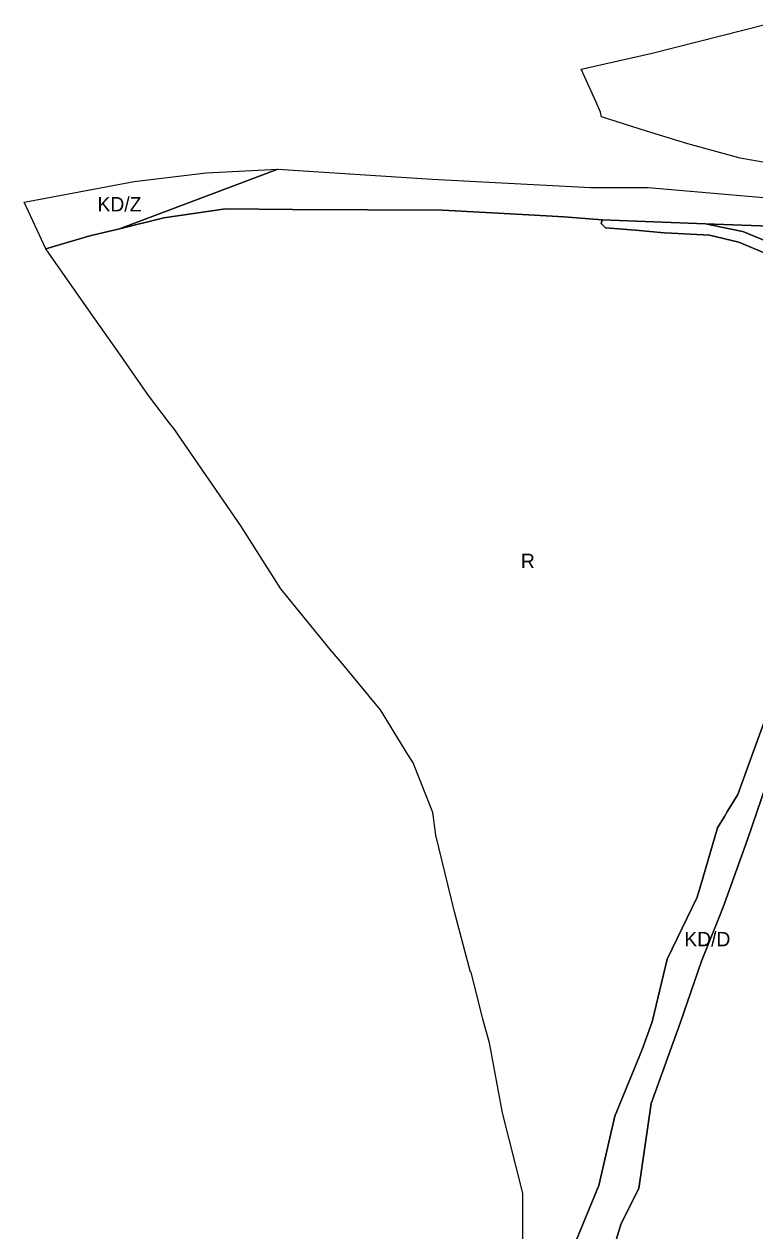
# Model space of a CAD drawing. Extents: x 7438199 to 7440548, y 5549253 to 5551017.
# Drawn here: x 7438199 to 7438706, y 5549912 to 5550749 of the extents above; entities that cross this region are included whole.
import ezdxf

# ---------------------------------------------------------------- set-up
doc = ezdxf.new("R2010")
doc.units = 0
doc.layers.add('linie_rozgraniczajace', color=7, linetype='Continuous')
doc.layers.add('oznaczenia_przeznaczen', color=7, linetype='Continuous')

msp = doc.modelspace()

# ---------------------------------------------------------------- linework, layer by layer
at = {"layer": 'linie_rozgraniczajace'}
for points in [[(7438724.59, 5550650.73), (7438695.64, 5550655.89), (7438659.54, 5550665.82), (7438630.71, 5550674.75), (7438599.57, 5550684.51), (7438598.9, 5550687.86), (7438595.81, 5550694.75), (7438585.51, 5550717.7), (7438594.79, 5550719.76), (7438634.69, 5550728.62), (7438713.89, 5550748.85)], [(7438265.38, 5550607.05), (7438375.26, 5550648.19), (7438482.17, 5550641.29), (7438592, 5550635.56), (7438598.21, 5550635.57), (7438631.96, 5550635.63), (7438719.92, 5550628.01)], [(7438545.03, 5549869.81), (7438545.17, 5549938.29), (7438531.07, 5549994.14), (7438521.86, 5550042.53), (7438517.4, 5550059.08), (7438509.15, 5550091.54), (7438508.68, 5550091.5), (7438497.77, 5550133.42), (7438484.75, 5550186.67), (7438482.61, 5550202.32), (7438468.98, 5550236.75), (7438465.25, 5550242.41), (7438446.34, 5550273.45), (7438446.12, 5550273.72), (7438419.97, 5550305.31), (7438411.8, 5550315.18), (7438377.36, 5550357.27), (7438349.63, 5550401.07), (7438303.17, 5550468.4), (7438300.13, 5550472.27), (7438285.54, 5550491.44), (7438264.41, 5550521.66), (7438245.6, 5550548.42), (7438214.27, 5550593), (7438244.74, 5550601.98), (7438265.38, 5550607.05), (7438296.06, 5550614.59), (7438338.91, 5550620.88), (7438385.44, 5550620.39), (7438489.33, 5550619.92), (7438519.34, 5550618.2), (7438549.07, 5550616.55), (7438573.42, 5550615.16), (7438600.01, 5550613.25), (7438599.47, 5550610.67), (7438602.36, 5550607.7), (7438623.13, 5550605.93), (7438642.95, 5550604.23), (7438648.22, 5550604.04), (7438674.54, 5550602.54), (7438694.83, 5550597.65), (7438713.52, 5550589.86)], [(7438894.22, 5550560.43), (7438887.92, 5550566.48), (7438888.89, 5550567.32), (7438879.39, 5550574.14), (7438873.06, 5550578.68), (7438866.73, 5550583.23), (7438852.19, 5550593.13), (7438838.54, 5550599.62), (7438797, 5550605.68), (7438761.69, 5550606.92), (7438737.96, 5550607.87), (7438716.87, 5550608.71), (7438696.99, 5550609.45), (7438671.7, 5550610.37), (7438600.01, 5550613.25), (7438573.42, 5550615.16), (7438549.07, 5550616.55), (7438519.34, 5550618.2), (7438489.33, 5550619.92), (7438385.44, 5550620.39), (7438338.91, 5550620.88), (7438296.06, 5550614.59), (7438265.38, 5550607.05)], [(7438713.52, 5550589.86), (7438694.83, 5550597.65), (7438674.54, 5550602.54), (7438648.22, 5550604.04), (7438642.95, 5550604.23), (7438623.13, 5550605.93), (7438602.36, 5550607.7), (7438599.47, 5550610.67), (7438600.01, 5550613.25), (7438671.7, 5550610.37), (7438696.25, 5550605.39), (7438697.63, 5550605.18), (7438714.95, 5550597.94)], [(7438716.44, 5550276.4), (7438702.92, 5550238.98), (7438694.2, 5550214.86), (7438687.05, 5550203.15), (7438684.87, 5550199.59), (7438680.01, 5550191.63), (7438669.82, 5550156.79), (7438665.98, 5550143.61), (7438645.21, 5550100.54), (7438636.25, 5550063.9), (7438634.62, 5550057.28), (7438627.81, 5550037.97), (7438608.83, 5549991.81), (7438597.73, 5549943.7), (7438581.96, 5549905.55)], [(7438581.96, 5549905.55), (7438597.73, 5549943.7), (7438608.83, 5549991.81), (7438627.81, 5550037.97), (7438634.62, 5550057.28), (7438636.25, 5550063.9), (7438645.21, 5550100.54), (7438665.98, 5550143.61), (7438669.82, 5550156.79), (7438680.01, 5550191.63), (7438684.87, 5550199.59), (7438687.05, 5550203.15), (7438694.2, 5550214.86), (7438702.92, 5550238.98), (7438716.44, 5550276.4)], [(7438600.02, 5549874.4), (7438613.31, 5549917.27), (7438625.44, 5549941.62), (7438634.15, 5550000.58), (7438654.37, 5550056.83), (7438668.91, 5550099.21), (7438683.92, 5550136.68), (7438700.83, 5550183.58), (7438719.95, 5550239.79)], [(7438719.95, 5550239.79), (7438700.83, 5550183.58), (7438683.92, 5550136.68), (7438668.91, 5550099.21), (7438654.37, 5550056.83), (7438634.15, 5550000.58), (7438625.44, 5549941.62), (7438613.31, 5549917.27), (7438600.02, 5549874.4)]]:
    msp.add_lwpolyline(points, dxfattribs=at)
for points in [[(7438199.3, 5550625.45), (7438275.57, 5550639.78), (7438325.48, 5550645.7), (7438375.26, 5550648.19), (7438265.38, 5550607.05), (7438244.74, 5550601.98), (7438214.27, 5550593)], [(7438671.7, 5550610.37), (7438696.99, 5550609.45), (7438716.87, 5550608.71), (7438737.96, 5550607.87), (7438761.69, 5550606.92), (7438755.95, 5550580.78), (7438734.69, 5550589.67), (7438714.95, 5550597.94), (7438697.63, 5550605.18), (7438696.25, 5550605.39)]]:
    msp.add_lwpolyline(points, close=True, dxfattribs=at)

# ---------------------------------------------------------------- texts
at = {"layer": 'oznaczenia_przeznaczen'}
for s, p in [('KD/Z', (7438250.18, 5550618.98)), ('R', (7438543.72, 5550371.69)), ('KD/D', (7438657, 5550109.52))]:
    msp.add_text(s, height=10, dxfattribs=at).set_placement(p)

doc.saveas('drawing.dxf')
